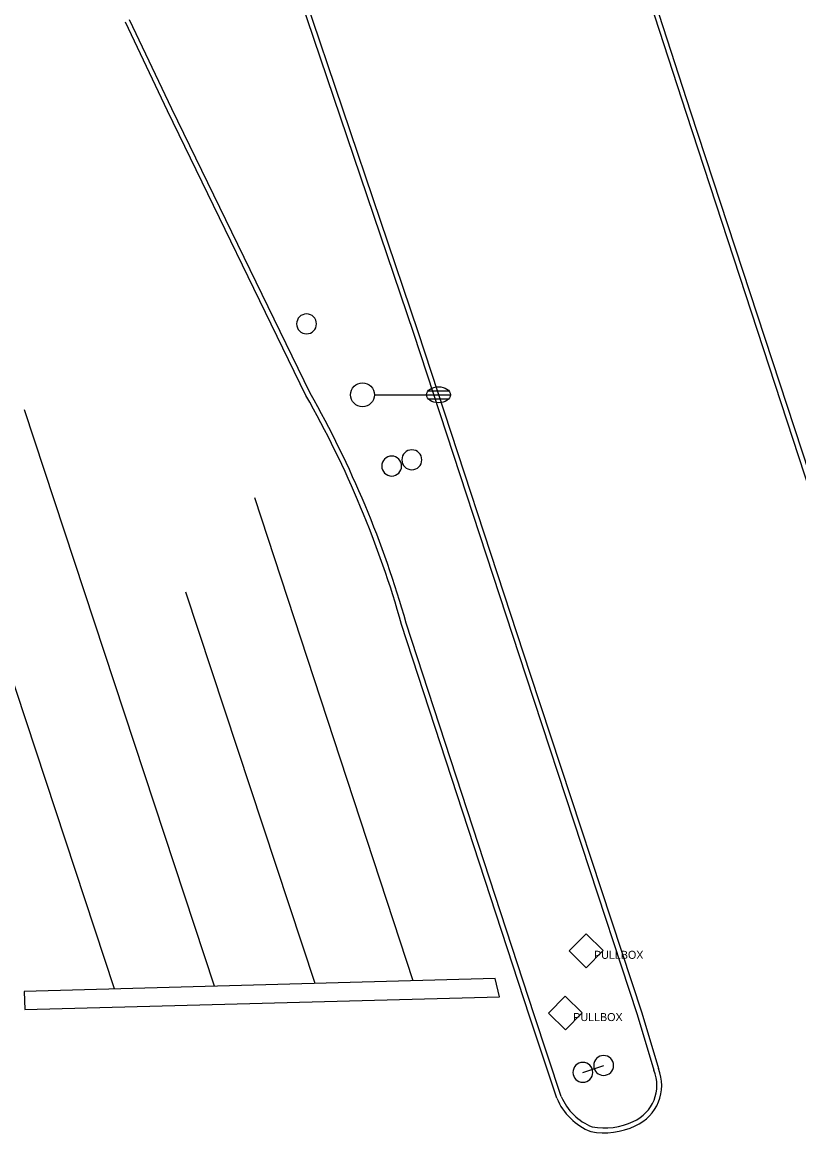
# Model space of a CAD drawing. Extents: x 2145380 to 2157287, y 139568 to 149130.
# Drawn here: x 2147230.8 to 2147327.9, y 143215 to 143353.8 of the extents above; entities that cross this region are included whole.
import ezdxf

# ---------------------------------------------------------------- set-up
doc = ezdxf.new("R2010")
doc.units = 0
for name, color, linetype in [('Default', 7, 'Continuous'), ('TOPO_Curb Back', 7, 'Continuous'), ('TOPO_Light Pole', 7, 'Continuous'), ('TOPO_Misc', 7, 'Continuous'), ('TOPO_Misc Line', 7, 'Continuous'), ('TOPO_Power Pullbox', 7, 'Continuous'), ('TOPO_Sign', 7, 'Continuous')]:
    doc.layers.add(name, color=color, linetype=linetype)

# ---------------------------------------------------------------- blocks, each defined once
blk = doc.blocks.new('LP')
at = {"layer": 'TOPO_Light Pole'}
blk.add_line((3.81, 0), (20.32, 0), dxfattribs=at)
for points in [[(20.32, 0), (27.94, 0)], [(20.32, 0), (23.5, 0)], [(20.83, 1.27), (27.43, 1.27)], [(20.83, 1.27), (23.5, 1.27)], [(23.71, 1.27), (27.43, 1.27)], [(23.71, 0), (27.94, 0)], [(20.83, -1.27), (27.43, -1.27)], [(20.83, -1.27), (23.5, -1.27)], [(23.71, -1.27), (27.43, -1.27)]]:
    blk.add_lwpolyline(points, dxfattribs=at)
blk.add_circle((0, 0), 3.81, dxfattribs=at)
blk.add_ellipse((24.13, 0), major_axis=(3.81, 0), ratio=0.666667, dxfattribs=at)
blk = doc.blocks.new('POST')
at = {"layer": 'TOPO_Misc'}
for start, end in [(90, 180), (180, 270), (360, 90), (270, 0)]:
    blk.add_arc((-0.01, 0.03), 3.16, start, end, dxfattribs=at)
blk = doc.blocks.new('pulbox')
at = {"layer": 'Default'}
blk.add_lwpolyline([(-5.38, -0.01), (-0.02, 5.42), (5.4, 0.06), (0.05, -5.36), (-5.38, -0.01)], dxfattribs=at)
blk.add_text('PULLBOX', height=2.54, dxfattribs=at).set_placement((2.54, -2.54))

msp = doc.modelspace()

# ---------------------------------------------------------------- linework, layer by layer
at = {"layer": 'TOPO_Curb Back'}
for p, q in [((2147265.53, 143356.75), (2147279.68, 143314.95)), ((2147266.1, 143356.94), (2147280.25, 143315.14)), ((2147249.5, 143342.97), (2147244.21, 143354.09)), ((2147248.96, 143342.71), (2147243.69, 143353.8)), ((2147266.77, 143307.42), (2147249.5, 143342.97)), ((2147266.24, 143307.14), (2147248.96, 143342.71)), ((2147280.25, 143315.14), (2147294.29, 143272.31)), ((2147279.68, 143314.95), (2147293.72, 143272.12)), ((2147294.19, 143229.56), (2147278.21, 143278.52)), ((2147294.76, 143229.75), (2147278.78, 143278.69)), ((2147293.72, 143272.12), (2147307.65, 143229.79)), ((2147294.29, 143272.31), (2147308.22, 143229.97)), ((2147297.61, 143219.32), (2147294.19, 143229.56)), ((2147298.17, 143219.53), (2147294.76, 143229.75)), ((2147307.65, 143229.79), (2147309.76, 143222.81)), ((2147308.22, 143229.97), (2147310.32, 143223.01))]:
    msp.add_line(p, q, dxfattribs=at)
for points in [[(2147293.8, 143402.61), (2147300.88, 143382.17), (2147313.77, 143342.42), (2147328.59, 143297.23), (2147344.02, 143251.18), (2147349.44, 143234.94)], [(2147294.36, 143402.8), (2147301.45, 143382.36), (2147314.34, 143342.61), (2147329.16, 143297.42), (2147344.59, 143251.38), (2147350, 143235.15)]]:
    msp.add_lwpolyline(points, dxfattribs=at)
for centre, radius, start, end in [((2147153.23, 143243.08), 129.91, 15.8284, 29.5461), ((2147153.23, 143243.08), 130.51, 15.8335, 29.5377), ((2147305.2, 143220.92), 4.93, 293.547, 22.5261), ((2147305.2, 143220.92), 5.53, 293.6433, 22.2073), ((2147304.67, 143222.26), 7.65, 202.6402, 248.5564), ((2147304.67, 143222.26), 7.05, 202.8146, 248.092), ((2147303.54, 143224.1), 9.11, 259.4676, 295.2436), ((2147303.54, 143224.1), 8.51, 259.8549, 295.3006)]:
    msp.add_arc(centre, radius, start, end, dxfattribs=at)
at = {"layer": 'TOPO_Misc Line'}
for p, q in [((2147254.8, 143233.31), (2147231.08, 143305.34)), ((2147279.67, 143234), (2147259.84, 143294.34)), ((2147267.42, 143233.66), (2147251.24, 143282.55))]:
    msp.add_line(p, q, dxfattribs=at)
msp.add_lwpolyline([(2147242.33, 143232.97), (2147210.41, 143329.68), (2147184.07, 143408.45), (2147169.19, 143453.56), (2147149.47, 143513.78), (2147117.99, 143609.55)], dxfattribs=at)
msp.add_lwpolyline([(2147231.09, 143230.39), (2147290.45, 143232), (2147289.92, 143234.28), (2147231.03, 143232.66)], close=True, dxfattribs=at)
at = {"layer": 'TOPO_Sign'}
msp.add_lwpolyline([(2147300.87, 143222.53), (2147303.47, 143223.39)], dxfattribs=at)

# ---------------------------------------------------------------- block references
at = {"layer": 'TOPO_Light Pole', "xscale": 0.39370000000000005, "yscale": 0.3937000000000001}
msp.add_blockref('LP', (2147273.32, 143307.23), dxfattribs=at)
at = {"layer": 'TOPO_Misc', "xscale": 0.39370000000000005, "yscale": 0.3937000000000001}
for p in [(2147266.33, 143316.08), (2147279.49, 143299.09), (2147276.97, 143298.31), (2147300.87, 143222.53), (2147303.47, 143223.39)]:
    msp.add_blockref('POST', p, dxfattribs=at)
at = {"layer": 'TOPO_Power Pullbox', "xscale": 0.39370000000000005, "yscale": 0.3937000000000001}
for p in [(2147301.27, 143237.73), (2147298.67, 143229.95)]:
    msp.add_blockref('pulbox', p, dxfattribs=at)

doc.saveas('drawing.dxf')
